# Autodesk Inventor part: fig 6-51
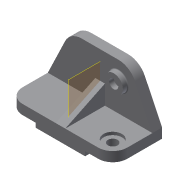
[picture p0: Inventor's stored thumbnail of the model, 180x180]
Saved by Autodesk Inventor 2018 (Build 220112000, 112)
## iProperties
Shininess: 77.0
Length Units: 11269
Angle Units: 11279
Time Units: 11290
Mass Units: 11283
Length Display Precision: 3
Angle Display Precision: 2
Created: 2001-12
Part Number: fig 6-51
Document SubType Name: Modeling
Designer: Renu Muthoo
Density: 1 g/cm^3
Material: Generic
Appearance: Default
Density: 0.0
Volumn: 0.0
Area: 0.0
PropertySet Name: Model Information
Control State: 0
Master: False
Checked Out: False
Author: Renu Muthoo
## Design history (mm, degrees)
node "Sketch1"
sketch "Sketch2"
  geometry: L1 (-67.219, 19.116)-(148.781, 19.116); L2 (148.781, 19.116)-(148.781, -0.884); L3 (-67.219, -0.884)-(-67.219, 19.116); L4 (-10.219, -0.884)-(-10.219, -9.884); L5 (-10.219, -9.884)-(91.781, -9.884); L6 (91.781, -9.884)-(91.781, -0.884); L7 (148.781, -0.884)-(91.781, -0.884); L8 (-10.219, -0.884)-(-67.219, -0.884)
  constraints: 16 end point, 5 parallel, 4 perpendicular, 2 equal length, 1 horizontal
  dimensions: "d0" = 102 distance of L4.end L5.end; "d1" = 57 distance of L4.start L3.start; "d2" = 29 distance between parallel lines of L1 L5; "d3" = 20 distance of L1.end L2.end
extrude "Extrusion1" new body sketch "Sketch2" distance "d4" = 102; taper "d5" = 0 deg
sketch "Sketch3"
  geometry: L1 (67.219, -19.116)-(-148.781, -19.116) reference; L2 (67.219, -19.116)-(31.475, -93.564); L3 (-2.781, -115.116)-(-78.781, -115.116); L4 (-113.038, -93.564)-(-148.781, -19.116); A1 r 38 centre (-2.781, -77.116) between (-2.781, -115.116) and (31.475, -93.564); A2 r 38 centre (-78.781, -77.116) between (-113.038, -93.564) and (-78.781, -115.116)
  constraints: 6 end point, 4 point on circle, 4 tangent, 2 centre point, 1 equal length, 1 equal radius, 1 parallel
  dimensions: "d6" = 96 distance between parallel lines of L3 L1; "d7" = 38 radius of A1; "d8" = 76 distance of A2.centre A1.centre
extrude "Extrusion2" join sketch "Sketch3" distance "d9" = 20; taper "d10" = 0 deg
fillet "Fillet1" dims "d11" = 30
workplane "Work Plane1"
sketch "Sketch5"
  geometry: A1 r 30 centre (-30, 0) between (-30, -30) and (0, 0) reference; 1 further point
  constraints: 1 coincident
hole "Hole1" sketch "Sketch5" at (-30, 0) diameter "d16" = 20; stored, may be unused: countersink angle "d20" = 82 deg, drill point angle "d22" = 118 deg; dims "d17" = 6, "d18" = 38, "d19" = 6, "d21" = 8
sketch "Sketch6"
  geometry: C1 r 19 at (-2.781, 77.116); C2 r 9.5 at (-2.781, 77.116); A1 r 38 centre (-2.781, 77.116) between (31.475, 93.564) and (-2.781, 115.116) reference
  constraints: 2 centre point, 2 coincident
  dimensions: "d23" = 38 diameter of C1; "d24" = 19 diameter of C2
extrude "Extrusion3" join sketch "Sketch6" distance "d25" = 10; taper "d26" = 0 deg
sketch "Sketch7"
  geometry: L1 (0, -82)-(-39.557, 0); L2 (0, -82)-(20, -82) reference; L3 (29, 22.405)-(29, -82); L4 (29, -82)-(0, -82); L5 (0, -82)-(0, 0); L6 (0, 0)-(-90.034, 0); L7 (-90.034, 0)-(-90.034, 22.405); L8 (-90.034, 22.405)-(29, 22.405); L9 (0, 0)-(-74.447, 0) reference
  constraints: 14 end point, 1 collinear, 1 point on line
feature "Rib3" sketch "Sketch7" dims "d35" = 10, "d36" = 20
fillet "Fillet3" dims "d37" = 2
body "Solid1"
other parameters: "d12" = -108
